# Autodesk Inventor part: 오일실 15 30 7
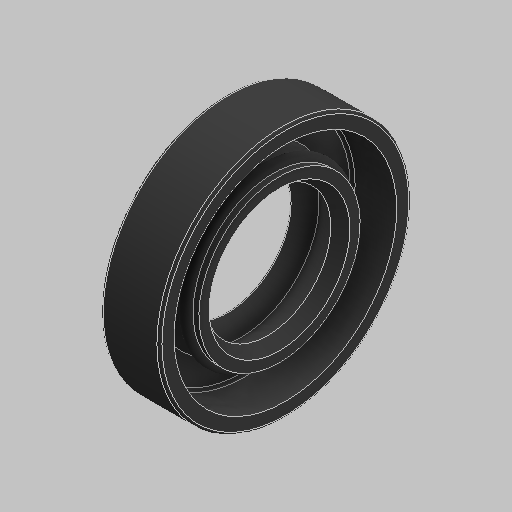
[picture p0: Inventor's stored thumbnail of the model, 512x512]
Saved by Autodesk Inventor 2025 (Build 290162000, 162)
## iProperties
Created: 2024-07
Part Number: 오일실 15 30 7
Material: 고무
Description: 오일-실
Document SubType Name: Modeling
Designer: 현기
Density: 0.93 g/cm^3
Appearance: 기본값
Author: jhkim
Sending System: Autodesk Inventor 2025
Preprocessor: ST-DEVELOPER v20
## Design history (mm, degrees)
feature "Solid1"
node "솔리드1"
